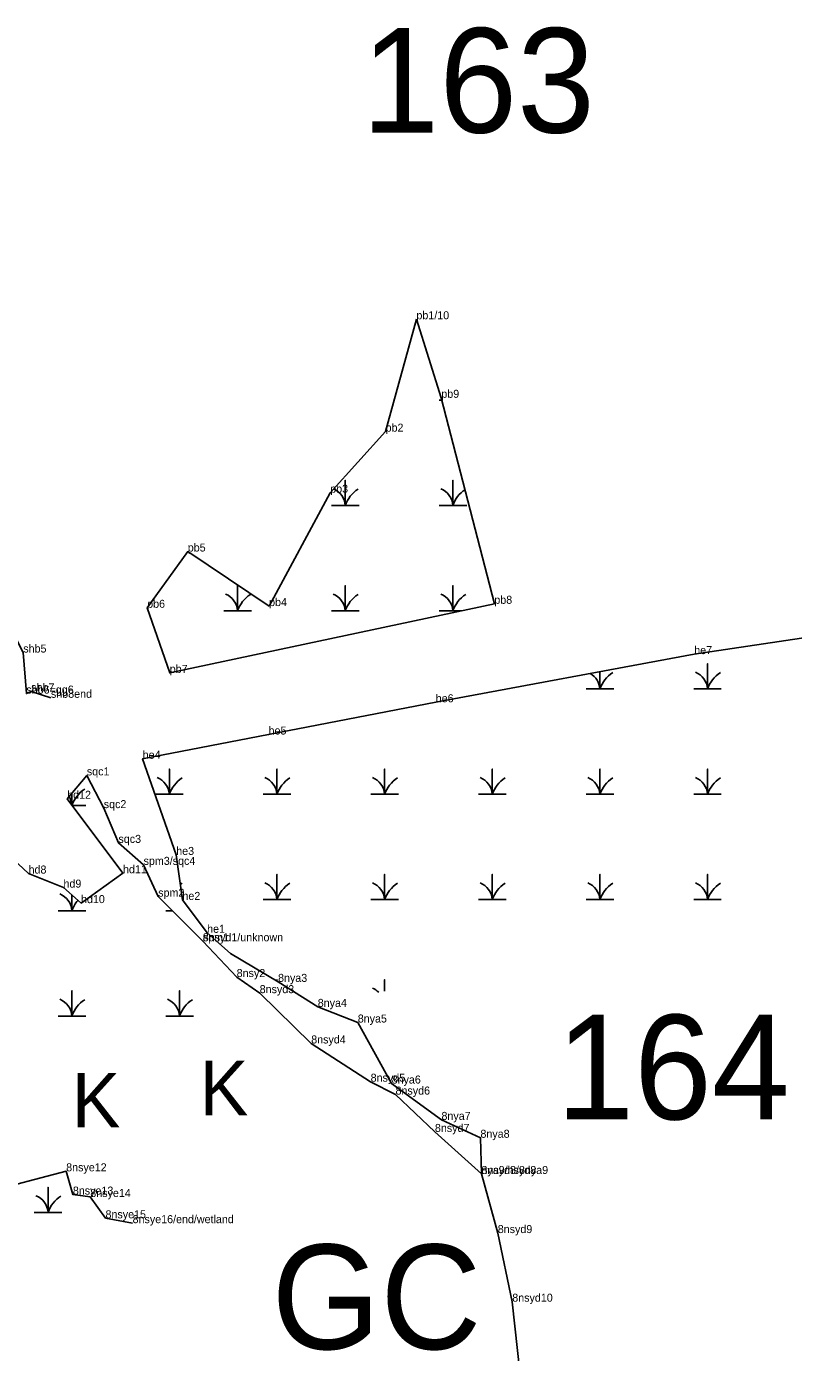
# Model space of a CAD drawing. Extents: x 2072529 to 2268796, y 436423 to 470406.
# Drawn here: x 2184317 to 2184796, y 452608 to 453437 of the extents above; entities that cross this region are included whole.
import ezdxf

# ---------------------------------------------------------------- set-up
doc = ezdxf.new("R2010")
doc.units = 0
for name, color, linetype in [('Default', 7, 'Continuous'), ('Exist Environmental Wetland Boundary Cogo Comment', 7, 'Continuous'), ('Exist Environmental Wetland Boundary Cogo Point CELL', 7, 'Continuous'), ('Exist Hydro Jurisdictional Stream or Body of Water NEU Mitigable Cogo Comment', 7, 'Continuous'), ('Old_Level_20', 7, 'Continuous'), ('Old_Level_52', 7, 'Continuous')]:
    doc.layers.add(name, color=color, linetype=linetype)

msp = doc.modelspace()

# ---------------------------------------------------------------- linework, layer by layer
at = {"layer": 'Exist Environmental Wetland Boundary Cogo Point CELL'}
for points in [[(2184575.02, 453203.24), (2184576.75, 453203.24)], [(2184507.77, 453137.44), (2184516.37, 453137.44), (2184516.37, 453153.22), (2184516.37, 453137.44), (2184524.98, 453137.44)], [(2184575.02, 453137.44), (2184583.62, 453137.44), (2184583.62, 453153.22), (2184583.62, 453137.44), (2184592.23, 453137.44)], [(2184440.52, 453071.64), (2184449.12, 453071.64), (2184449.12, 453087.42), (2184449.12, 453071.64), (2184457.73, 453071.64)], [(2184507.77, 453071.64), (2184516.37, 453071.64), (2184516.37, 453087.42), (2184516.37, 453071.64), (2184524.98, 453071.64)], [(2184575.02, 453071.64), (2184583.62, 453071.64), (2184583.62, 453087.42), (2184583.62, 453071.64), (2184588.88, 453071.64)], [(2184666.85, 453022.81), (2184675.45, 453022.81), (2184675.45, 453033.62)], [(2184675.45, 453033.62), (2184675.45, 453022.81), (2184684.05, 453022.81)], [(2184734.1, 453022.81), (2184742.7, 453022.81), (2184742.7, 453038.59), (2184742.7, 453022.81), (2184751.3, 453022.81)], [(2184397.85, 452957.01), (2184406.45, 452957.01), (2184406.45, 452972.79), (2184406.45, 452957.01), (2184415.05, 452957.01)], [(2184465.1, 452957.01), (2184473.7, 452957.01), (2184473.7, 452972.79), (2184473.7, 452957.01), (2184482.3, 452957.01)], [(2184532.35, 452957.01), (2184540.95, 452957.01), (2184540.95, 452972.79), (2184540.95, 452957.01), (2184549.55, 452957.01)], [(2184599.6, 452957.01), (2184608.2, 452957.01), (2184608.2, 452972.79), (2184608.2, 452957.01), (2184616.8, 452957.01)], [(2184666.85, 452957.01), (2184675.45, 452957.01), (2184675.45, 452972.79), (2184675.45, 452957.01), (2184684.05, 452957.01)], [(2184734.1, 452957.01), (2184742.7, 452957.01), (2184742.7, 452972.79), (2184742.7, 452957.01), (2184751.3, 452957.01)], [(2184345.6, 452950.28), (2184345.6, 452957.74)], [(2184345.6, 452957.74), (2184345.6, 452950.28)], [(2184345.76, 452950.07), (2184354.2, 452950.07)], [(2184465.1, 452891.21), (2184473.7, 452891.21), (2184473.7, 452906.99), (2184473.7, 452891.21), (2184482.3, 452891.21)], [(2184532.35, 452891.21), (2184540.95, 452891.21), (2184540.95, 452906.99), (2184540.95, 452891.21), (2184549.55, 452891.21)], [(2184599.6, 452891.21), (2184608.2, 452891.21), (2184608.2, 452906.99), (2184608.2, 452891.21), (2184616.8, 452891.21)], [(2184666.85, 452891.21), (2184675.45, 452891.21), (2184675.45, 452906.99), (2184675.45, 452891.21), (2184684.05, 452891.21)], [(2184734.1, 452891.21), (2184742.7, 452891.21), (2184742.7, 452906.99), (2184742.7, 452891.21), (2184751.3, 452891.21)], [(2184337, 452884.27), (2184345.6, 452884.27), (2184345.6, 452894.04)], [(2184345.6, 452894.04), (2184345.6, 452884.27), (2184354.2, 452884.27)], [(2184404.25, 452884.27), (2184408.3, 452884.27)], [(2184414.59, 452891.21), (2184415.05, 452891.21)], [(2184337, 452818.47), (2184345.6, 452818.47), (2184345.6, 452834.25), (2184345.6, 452818.47), (2184354.2, 452818.47)], [(2184404.25, 452818.47), (2184412.85, 452818.47), (2184412.85, 452834.25), (2184412.85, 452818.47), (2184421.45, 452818.47)], [(2184473.7, 452840.23), (2184473.7, 452841.19), (2184473.7, 452840.23)], [(2184540.95, 452834.12), (2184540.95, 452841.19), (2184540.95, 452834.12)], [(2184322.09, 452695.79), (2184330.69, 452695.79), (2184330.69, 452711.57), (2184330.69, 452695.79), (2184339.29, 452695.79)]]:
    msp.add_lwpolyline(points, dxfattribs=at)
for centre, radius, start, end in [((2184504.11, 453136.55), 12.3, 4.14034, 66.14686), ((2184534.62, 453131.38), 19.22, 122.12745, 161.62219), ((2184571.36, 453136.55), 12.3, 4.14034, 67.53497), ((2184601.87, 453131.38), 19.22, 123.9227, 161.62219), ((2184436.86, 453070.75), 12.3, 4.14034, 67.53497), ((2184467.37, 453065.58), 19.22, 122.12745, 161.62219), ((2184504.11, 453070.75), 12.3, 4.14034, 67.53497), ((2184534.62, 453065.58), 19.22, 122.12745, 161.62219), ((2184571.36, 453070.75), 12.3, 4.14034, 67.53497), ((2184601.87, 453065.58), 19.22, 122.12745, 161.62219), ((2184663.18, 453021.92), 12.3, 4.14034, 59.32388), ((2184693.69, 453016.75), 19.22, 122.12745, 161.62219), ((2184730.43, 453021.92), 12.3, 4.14034, 67.53497), ((2184760.94, 453016.75), 19.22, 122.12745, 161.62219), ((2184394.18, 452956.12), 12.3, 4.14034, 67.53497), ((2184424.69, 452950.95), 19.22, 122.12745, 161.62219), ((2184461.43, 452956.12), 12.3, 4.14034, 67.53497), ((2184491.94, 452950.95), 19.22, 122.12745, 161.62219), ((2184528.68, 452956.12), 12.3, 4.14034, 67.53497), ((2184559.19, 452950.95), 19.22, 122.12745, 161.62219), ((2184595.93, 452956.12), 12.3, 4.14034, 67.53497), ((2184626.44, 452950.95), 19.22, 122.12745, 161.62219), ((2184663.18, 452956.12), 12.3, 4.14034, 67.53497), ((2184693.69, 452950.95), 19.22, 122.12745, 161.62219), ((2184730.43, 452956.12), 12.3, 4.14034, 67.53497), ((2184760.94, 452950.95), 19.22, 122.12745, 161.62219), ((2184363.84, 452944.01), 19.22, 122.12745, 161.16653), ((2184333.33, 452949.18), 12.3, 5.24272, 31.55116), ((2184424.69, 452885.15), 19.22, 122.12745, 126.37282), ((2184461.43, 452890.32), 12.3, 4.14034, 67.53497), ((2184491.94, 452885.15), 19.22, 122.12745, 161.62219), ((2184528.68, 452890.32), 12.3, 4.14034, 67.53497), ((2184559.19, 452885.15), 19.22, 122.12745, 161.62219), ((2184595.93, 452890.32), 12.3, 4.14034, 67.53497), ((2184626.44, 452885.15), 19.22, 122.12745, 161.62219), ((2184663.18, 452890.32), 12.3, 4.14034, 67.53497), ((2184693.69, 452885.15), 19.22, 122.12745, 161.62219), ((2184730.43, 452890.32), 12.3, 4.14034, 67.53497), ((2184760.94, 452885.15), 19.22, 122.12745, 161.62219), ((2184333.33, 452883.38), 12.3, 4.14034, 67.53497), ((2184363.84, 452878.21), 19.22, 139.18973, 161.62219), ((2184491.94, 452819.35), 19.22, 122.12745, 123.31524), ((2184528.68, 452824.52), 12.3, 45.98201, 67.53497), ((2184333.33, 452817.58), 12.3, 4.14034, 67.53497), ((2184363.84, 452812.41), 19.22, 122.12745, 161.62219), ((2184400.58, 452817.58), 12.3, 4.14034, 67.53497), ((2184431.09, 452812.41), 19.22, 122.12745, 161.62219), ((2184318.42, 452694.9), 12.3, 4.14034, 67.53497), ((2184348.93, 452689.73), 19.22, 122.12745, 161.62219)]:
    msp.add_arc(centre, radius, start, end, dxfattribs=at)
at = {"layer": 'Old_Level_20'}
for p, q in [((2184560.82, 453253.79), (2184560.82, 453253.79)), ((2184576.37, 453204.72), (2184576.37, 453204.72)), ((2184541.56, 453183.59), (2184541.56, 453183.59)), ((2184506.94, 453145.43), (2184506.94, 453145.43)), ((2184417.97, 453108.68), (2184417.97, 453108.68)), ((2184468.77, 453074.61), (2184468.77, 453074.61)), ((2184609.49, 453076.03), (2184609.49, 453076.03)), ((2184392.59, 453073.54), (2184392.59, 453073.54)), ((2184734.36, 453044.59), (2184734.36, 453044.59)), ((2184406.71, 453032.86), (2184406.71, 453032.86)), ((2184320.18, 453021.34), (2184320.18, 453021.34)), ((2184332.48, 453017.31), (2184332.48, 453017.31)), ((2184572.88, 453014.51), (2184572.88, 453014.51)), ((2184468.45, 452994.37), (2184468.45, 452994.37)), ((2184389.78, 452979.2), (2184389.78, 452979.2)), ((2184354.92, 452968.83), (2184354.92, 452968.83)), ((2184342.64, 452954.22), (2184342.64, 452954.22)), ((2184365.47, 452948.37), (2184365.47, 452948.37)), ((2184374.66, 452926.66), (2184374.66, 452926.66)), ((2184410.74, 452919.14), (2184410.74, 452919.14)), ((2184390.34, 452912.94), (2184390.34, 452912.94)), ((2184318.51, 452907.5), (2184318.51, 452907.5)), ((2184377.49, 452907.7), (2184377.49, 452907.7)), ((2184340.31, 452898.72), (2184340.31, 452898.72)), ((2184399.49, 452893.1), (2184399.49, 452893.1)), ((2184351.26, 452889.03), (2184351.26, 452889.03)), ((2184414.61, 452891.04), (2184414.61, 452891.04)), ((2184430.06, 452870.49), (2184430.06, 452870.49)), ((2184427.35, 452865.2), (2184427.35, 452865.2)), ((2184427.35, 452865.2), (2184427.35, 452865.2)), ((2184448.52, 452842.85), (2184448.52, 452842.85)), ((2184474.37, 452839.83), (2184474.37, 452839.83)), ((2184462.89, 452832.78), (2184462.89, 452832.78)), ((2184499.17, 452824.21), (2184499.17, 452824.21)), ((2184524.17, 452814.44), (2184524.17, 452814.44)), ((2184495.09, 452801.36), (2184495.09, 452801.36)), ((2184532.22, 452777.48), (2184532.22, 452777.48)), ((2184545.33, 452776.31), (2184545.33, 452776.31)), ((2184547.75, 452769.42), (2184547.75, 452769.42)), ((2184576.46, 452753.6), (2184576.46, 452753.6)), ((2184572.37, 452746.08), (2184572.37, 452746.08)), ((2184600.81, 452742.44), (2184600.81, 452742.44)), ((2184342, 452721.5), (2184342, 452721.5)), ((2184601.45, 452719.81), (2184601.45, 452719.81)), ((2184601.45, 452719.81), (2184601.45, 452719.81)), ((2184601.45, 452719.81), (2184601.45, 452719.81)), ((2184601.45, 452719.81), (2184601.45, 452719.81)), ((2184346.18, 452706.95), (2184346.18, 452706.95)), ((2184357.08, 452705.45), (2184357.08, 452705.45)), ((2184366.57, 452692.14), (2184366.57, 452692.14)), ((2184383.5, 452689.09), (2184383.5, 452689.09)), ((2184611.63, 452682.9), (2184611.63, 452682.9)), ((2184620.69, 452640.03), (2184620.69, 452640.03))]:
    msp.add_line(p, q, dxfattribs=at)
for points in [[(2184560.82, 453253.79), (2184576.37, 453204.72), (2184609.49, 453076.03), (2184406.71, 453032.86), (2184392.59, 453073.54), (2184417.97, 453108.68), (2184468.77, 453074.61), (2184506.94, 453145.43), (2184541.56, 453183.59), (2184560.82, 453253.79)], [(2184430.06, 452870.49), (2184414.61, 452891.04), (2184410.74, 452919.14), (2184389.78, 452979.2), (2184468.45, 452994.37), (2184572.88, 453014.51), (2184734.36, 453044.59), (2184844.78, 453061.05), (2184879.9, 453033.18), (2184921.85, 453038.15), (2184950.29, 453026.71), (2185005.39, 452975.93), (2185089.84, 452940.32), (2185140.72, 452908), (2185212.43, 452875.12), (2185257.21, 452851.43), (2185297.24, 452872.01), (2185336.35, 452934.49), (2185366.6, 452975.91), (2185379.38, 453038.1), (2185384.73, 453120.74)], [(2184430.06, 452870.49), (2184414.61, 452891.04), (2184410.74, 452919.14), (2184389.78, 452979.2), (2184468.45, 452994.37), (2184572.88, 453014.51), (2184734.36, 453044.59), (2184844.78, 453061.05)], [(2184342.64, 452954.22), (2184354.92, 452968.83), (2184365.47, 452948.37), (2184374.66, 452926.66), (2184390.34, 452912.94), (2184399.49, 452893.1), (2184427.35, 452865.2)], [(2184342.64, 452954.22), (2184377.49, 452907.7), (2184351.26, 452889.03), (2184340.31, 452898.72), (2184318.51, 452907.5), (2184305.63, 452919.59), (2184281.2, 452926.35), (2184235.29, 452908.62), (2184218.7, 452882.98), (2184210.93, 452832.58), (2184213.95, 452800.56), (2184203.13, 452729.67), (2184195.27, 452705.58)], [(2184430.06, 452870.49), (2184444.76, 452857.65), (2184474.37, 452839.83), (2184499.17, 452824.21), (2184524.17, 452814.44), (2184545.33, 452776.31), (2184576.46, 452753.6), (2184600.81, 452742.44), (2184601.45, 452719.81)]]:
    msp.add_lwpolyline(points, dxfattribs=at)
at = {"layer": 'Old_Level_52'}
for points in [[(2184237.77, 453185.47), (2184260.36, 453161.16), (2184292.62, 453119.01), (2184281.81, 453101.74), (2184295.32, 453083.73), (2184315.19, 453045.58), (2184317.13, 453019.93), (2184320.18, 453021.34), (2184332.48, 453017.31)], [(2184354.92, 452968.83), (2184365.47, 452948.37), (2184374.66, 452926.66), (2184390.34, 452912.94), (2184399.49, 452893.1), (2184427.35, 452865.2)], [(2184427.35, 452865.2), (2184448.52, 452842.85), (2184462.89, 452832.78), (2184495.09, 452801.36), (2184532.22, 452777.48), (2184547.75, 452769.42), (2184572.37, 452746.08), (2184601.45, 452719.81), (2184611.63, 452682.9), (2184620.69, 452640.03), (2184625.62, 452594.37)], [(2184383.5, 452689.09), (2184366.57, 452692.14), (2184357.08, 452705.45), (2184346.18, 452706.95), (2184342, 452721.5), (2184291.25, 452708.24), (2184243.71, 452715.43), (2184195.27, 452705.58), (2184141.22, 452692.72), (2184091.73, 452688.49)]]:
    msp.add_lwpolyline(points, dxfattribs=at)

# ---------------------------------------------------------------- texts
at = {"layer": 'Default'}
for s, p in [('163', (2184526.52, 453370.36)), ('164', (2184648.19, 452753.94)), ('GC', (2184470.33, 452610.38))]:
    msp.add_text(s, height=65.34, dxfattribs=at).set_placement(p)
at = {"layer": 'Exist Environmental Wetland Boundary Cogo Comment'}
for s, p in [('pb1/10', (2184560.82, 453253.79)), ('pb9', (2184576.37, 453204.72)), ('pb2', (2184541.56, 453183.59)), ('pb3', (2184506.94, 453145.43)), ('pb5', (2184417.97, 453108.68)), ('pb6', (2184392.59, 453073.54)), ('pb4', (2184468.77, 453074.61)), ('pb8', (2184609.49, 453076.03)), ('he7', (2184734.36, 453044.59)), ('pb7', (2184406.71, 453032.86)), ('he6', (2184572.88, 453014.51)), ('he5', (2184468.45, 452994.37)), ('he4', (2184389.78, 452979.2)), ('hd12', (2184342.64, 452954.22)), ('he3', (2184410.74, 452919.14)), ('hd8', (2184318.51, 452907.5)), ('hd11', (2184377.49, 452907.7)), ('hd9', (2184340.31, 452898.72)), ('hd10', (2184351.26, 452889.03)), ('he2', (2184414.61, 452891.04)), ('he1', (2184430.06, 452870.49))]:
    msp.add_text(s, height=5, dxfattribs=at).set_placement(p)
at = {"layer": 'Exist Environmental Wetland Boundary Cogo Point CELL'}
for p in [(2184425.43, 452756.51), (2184345.51, 452748.99)]:
    msp.add_text('K', height=34, dxfattribs=at).set_placement(p)
at = {"layer": 'Exist Hydro Jurisdictional Stream or Body of Water NEU Mitigable Cogo Comment'}
for s, p in [('shb5', (2184315.19, 453045.58)), ('shb6=gg6', (2184317.13, 453019.93)), ('shb7', (2184320.18, 453021.34)), ('shb8end', (2184332.48, 453017.31)), ('sqc1', (2184354.92, 452968.83)), ('sqc2', (2184365.47, 452948.37)), ('sqc3', (2184374.66, 452926.66)), ('spm3/sqc4', (2184390.34, 452912.94)), ('spm2', (2184399.49, 452893.1)), ('spm1', (2184427.35, 452865.2)), ('8nsyd1/unknown', (2184427.35, 452865.2)), ('8nsy2', (2184448.52, 452842.85)), ('8nya3', (2184474.37, 452839.83)), ('8nsyd3', (2184462.89, 452832.78)), ('8nya4', (2184499.17, 452824.21)), ('8nya5', (2184524.17, 452814.44)), ('8nsyd4', (2184495.09, 452801.36)), ('8nsyd5', (2184532.22, 452777.48)), ('8nya6', (2184545.33, 452776.31)), ('8nsyd6', (2184547.75, 452769.42)), ('8nsyd7', (2184572.37, 452746.08)), ('8nya7', (2184576.46, 452753.6)), ('8nya8', (2184600.81, 452742.44)), ('8nsye12', (2184342, 452721.5)), ('8nsyd8/8nya9', (2184601.45, 452719.81)), ('nya9/nsyd8', (2184601.45, 452719.81)), ('8nsye13', (2184346.18, 452706.95)), ('8nsye14', (2184357.08, 452705.45)), ('8nsye15', (2184366.57, 452692.14)), ('8nsye16/end/wetland', (2184383.5, 452689.09)), ('8nsyd9', (2184611.63, 452682.9)), ('8nsyd10', (2184620.69, 452640.03))]:
    msp.add_text(s, height=5, dxfattribs=at).set_placement(p)

doc.saveas('drawing.dxf')
